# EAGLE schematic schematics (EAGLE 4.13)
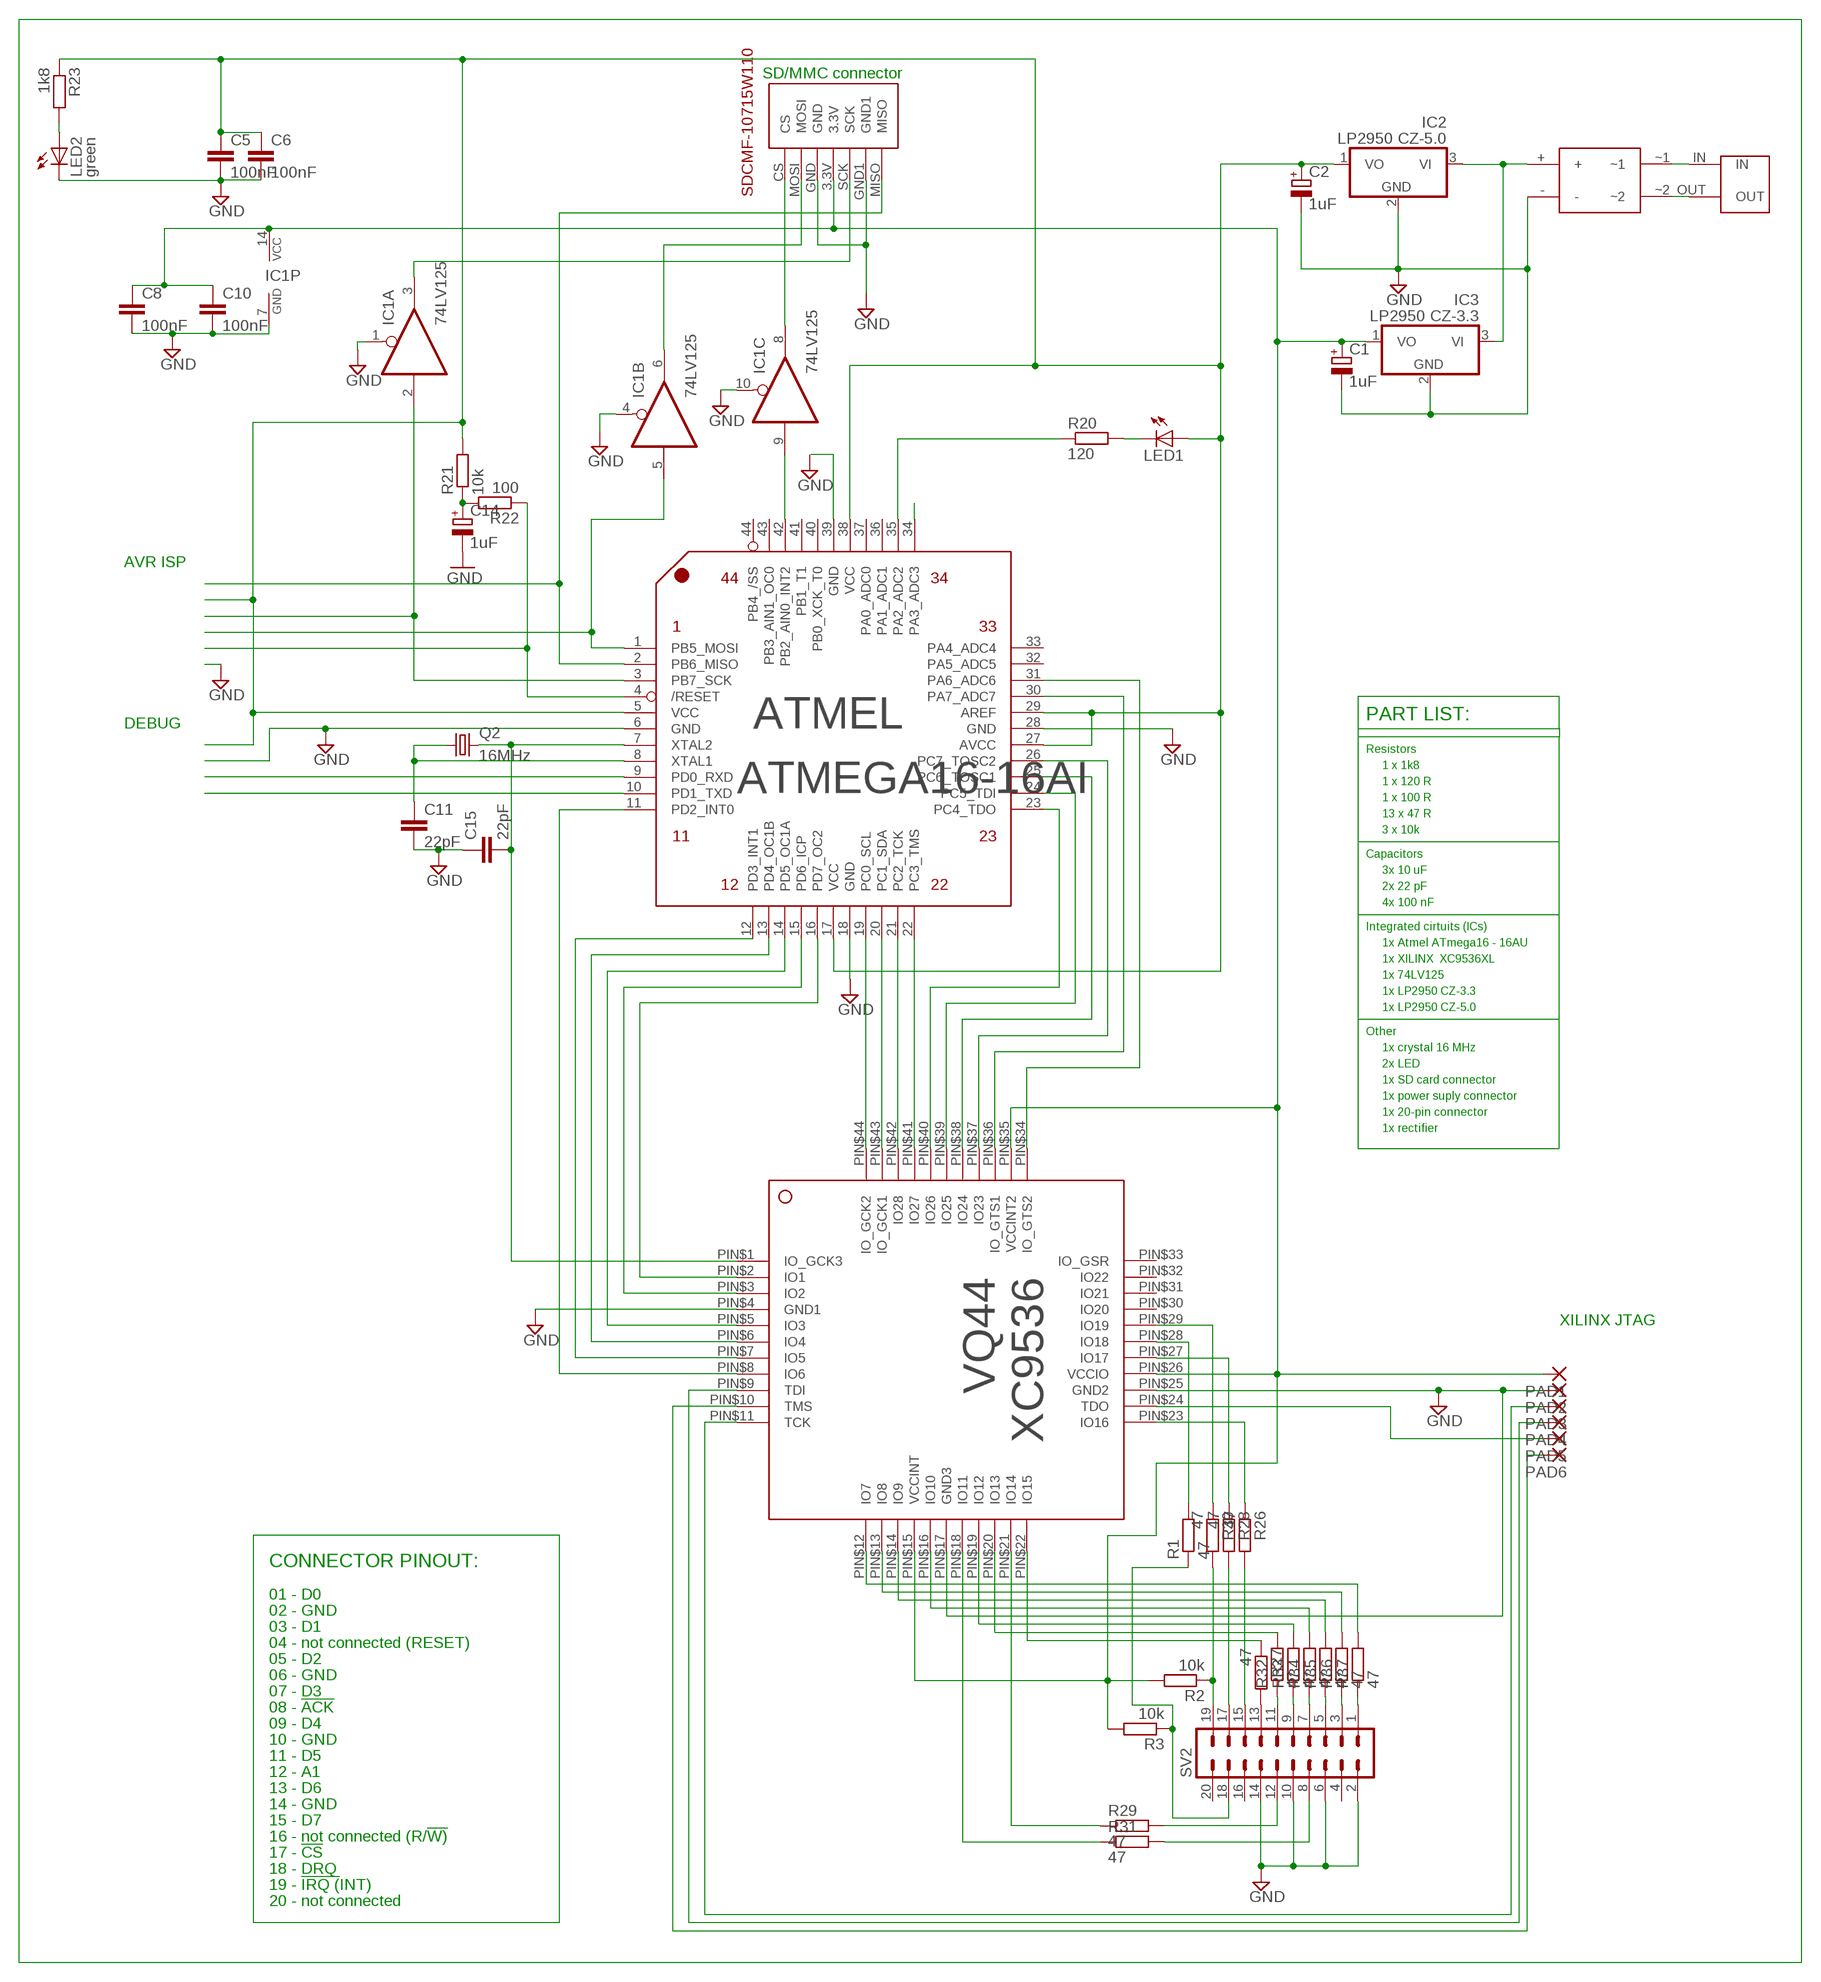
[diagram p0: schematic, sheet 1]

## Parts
ATMEL  ATMEGA16-16AI  [TQFP-44]
C1  1uF  CPOL-EUE2,5-6E  [E2,5-6E]
C2  1uF  CPOL-EUE2,5-6E  [E2,5-6E]
C5  100nF  C-EUC0805K  [C0805K]
C6  100nF  C-EUC0805K  [C0805K]
C8  100nF  C-EUC0805K  [C0805K]
C10  100nF  C-EUC0805K  [C0805K]
C11  22pF  C-EUC0805K  [C0805K]
C14  1uF  CPOL-EUE2-5  [E2-5]
C15  22pF  C-EUC0805K  [C0805K]
CON  DC_CON  [DC_CON]
IC1  74LV125  74HC125D  [SO14]
IC2  LP2950 CZ-5.0  7805L  [TO92]
IC3  LP2950 CZ-3.3  7805L  [TO92]
LED1  LED3MM  [LED3MM]
LED2  green  LED3MM  [LED3MM]
MMC  MMC_CONNECTOR  [MMC]
PAD1  SMD2  [SMD2]
PAD2  SMD2  [SMD2]
PAD3  SMD2  [SMD2]
PAD4  SMD2  [SMD2]
PAD5  SMD2  [SMD2]
PAD6  SMD2  [SMD2]
Q2  16MHz  CRYTALHC49S  [HC49/S]
R1  47  R-EU_M0805  [M0805]
R2  10k  R-EU_M0805  [M0805]
R3  10k  R-EU_M0805  [M0805]
R20  120  R-EU_M0805  [M0805]
R21  10k  R-EU_M0805  [M0805]
R22  100  R-EU_M0805  [M0805]
R23  1k8  R-EU_M0805  [M0805]
R26  47  R-EU_M0805  [M0805]
R27  47  R-EU_M0805  [M0805]
R28  47  R-EU_M0805  [M0805]
R29  47  R-EU_M0805  [M0805]
R30  47  R-EU_M0805  [M0805]
R31  47  R-EU_M0805  [M0805]
R32  47  R-EU_M0805  [M0805]
R33  47  R-EU_M0805  [M0805]
R34  47  R-EU_M0805  [M0805]
R35  47  R-EU_M0805  [M0805]
R36  47  R-EU_M0805  [M0805]
R37  47  R-EU_M0805  [M0805]
RECT  S80  B80_SMDSMALL  [SMD_B40]
SV2  ML20L  [ML20L]
XILINX  XC9536-VQ44  [VQ44]

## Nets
3.3V: C1.+ C8.1 C10.1 IC1.14(P:VCC) IC3.1(VO) MMC.3.3V PAD1.1(P) R2.2 R3.2 XILINX.PIN$15(VCCINT) XILINX.PIN$26(VCCIO) XILINX.PIN$35(VCCINT2)
5V: ATMEL.5(VCC) ATMEL.17(VCC) ATMEL.27(AVCC) ATMEL.29(AREF) ATMEL.38(VCC) C2.+ C5.1 C6.1 IC2.1(VO) LED1.A R21.2 R23.1
ACK: R1.2 XILINX.PIN$28(IO18)
AD0: R37.2 XILINX.PIN$12(IO7)
AD1: R36.2 XILINX.PIN$13(IO8)
AD2: R35.2 XILINX.PIN$14(IO9)
AD3: R34.2 XILINX.PIN$16(IO10)
AD4: R28.1 XILINX.PIN$27(IO17)
AD5: R26.1 XILINX.PIN$23(IO16)
AD6: R29.1 XILINX.PIN$21(IO14)
AD7: R32.2 XILINX.PIN$20(IO13)
CLK: ATMEL.7(XTAL2) C15.2 Q2.2 XILINX.PIN$1(IO_GCK3)
CS: R33.2 XILINX.PIN$19(IO12)
DRQ: R31.1 XILINX.PIN$18(IO11)
GND: ATMEL.6(GND) ATMEL.18(GND) ATMEL.28(GND) ATMEL.39(GND) C1.- C2.- C5.2 C6.2 C8.2 C10.2 C11.2 C14.- C15.1 IC1.1(A:OE) IC1.4(B:OE) IC1.7(P:GND) IC1.10(C:OE) IC2.2(GND) IC3.2(GND) LED2.K(C) MMC.GND MMC.GND1 PAD2.1(P) RECT.- SV2.2 SV2.6 SV2.10 SV2.14 XILINX.PIN$4(GND1) XILINX.PIN$17(GND3) XILINX.PIN$25(GND2)
N$1: ATMEL.35(PA2_ADC2) R20.1
N$2: ATMEL.19(PC0_SCL) XILINX.PIN$44(IO_GCK2)
N$3: ATMEL.20(PC1_SDA) XILINX.PIN$43(IO_GCK1)
N$4: ATMEL.21(PC2_TCK) XILINX.PIN$42(IO28)
N$5: ATMEL.22(PC3_TMS) XILINX.PIN$41(IO27)
N$6: ATMEL.23(PC4_TDO) XILINX.PIN$40(IO26)
N$7: ATMEL.24(PC5_TDI) XILINX.PIN$39(IO25)
N$8: ATMEL.25(PC6_TOSC1) XILINX.PIN$38(IO24)
N$9: ATMEL.26(PC7_TOSC2) XILINX.PIN$37(IO23)
N$10: ATMEL.30(PA7_ADC7) XILINX.PIN$36(IO_GTS1)
N$11: ATMEL.31(PA6_ADC6) XILINX.PIN$34(IO_GTS2)
N$12: ATMEL.16(PD7_OC2) XILINX.PIN$2(IO1)
N$13: ATMEL.15(PD6_ICP) XILINX.PIN$3(IO2)
N$14: ATMEL.14(PD5_OC1A) XILINX.PIN$5(IO3)
N$15: ATMEL.11(PD2_INT0) XILINX.PIN$8(IO6)
N$16: ATMEL.13(PD4_OC1B) XILINX.PIN$6(IO4)
N$17: ATMEL.12(PD3_INT1) XILINX.PIN$7(IO5)
N$18: R27.2 SV2.13
N$19: R26.2 SV2.15
N$20: R28.2 SV2.17
N$21: R2.1 R30.2 SV2.19
N$22: R29.2 SV2.12
N$23: R31.2 SV2.8
N$24: R32.1 SV2.11
N$25: R33.1 SV2.9
N$26: R34.1 SV2.7
N$27: R35.1 SV2.5
N$28: R36.1 SV2.3
N$29: R37.1 SV2.1
N$31: ATMEL.10(PD1_TXD)
N$32: ATMEL.9(PD0_RXD)
N$33: C14.+ R21.1 R22.2
N$34: PAD3.1(P) XILINX.PIN$11(TCK)
N$35: PAD5.1(P) XILINX.PIN$24(TDO)
N$36: PAD4.1(P) XILINX.PIN$9(TDI)
N$37: PAD6.1(P) XILINX.PIN$10(TMS)
N$38: ATMEL.34(PA3_ADC3)
N$40: ATMEL.8(XTAL1) C11.1 Q2.1
N$44: LED2.A R23.2
N$45: ATMEL.2(PB6_MISO) MMC.MISO
N$47: LED1.K(C) R20.2
N$49: ATMEL.4(/RESET) R22.1
N$50: R27.1 XILINX.PIN$22(IO15)
N$51: ATMEL.42(PB2_AIN0_INT2) IC1.9(C:I)
N$52: IC1.8(C:O) MMC.CS
N$53: ATMEL.1(PB5_MOSI) IC1.5(B:I)
N$54: IC1.6(B:O) MMC.MOSI
N$55: ATMEL.3(PB7_SCK) IC1.2(A:I)
N$56: IC1.3(A:O) MMC.SCK
N$57: R1.1 R3.1 SV2.18
N$58: R30.1 XILINX.PIN$29(IO19)
URAW: IC2.3(VI) IC3.3(VI) RECT.+
~1: CON.IN RECT.~1
~2: CON.OUT RECT.~2
Unconnected: ATMEL.32(PA5_ADC5) ATMEL.33(PA4_ADC4) ATMEL.36(PA1_ADC1) ATMEL.37(PA0_ADC0) ATMEL.40(PB0_XCK_T0) ATMEL.41(PB1_T1) ATMEL.43(PB3_AIN1_OC0) ATMEL.44(PB4_/SS) IC1.11(D:O) IC1.12(D:I) IC1.13(D:OE) SV2.4 SV2.16 SV2.20 XILINX.PIN$30(IO20) XILINX.PIN$31(IO21) XILINX.PIN$32(IO22) XILINX.PIN$33(IO_GSR)

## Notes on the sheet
- SD/MMC connector
- AVR ISP
- PART LIST:
- DEBUG
- Resistors
- 1 x 1k8
- 1 x 120 R
- 1 x 100 R
- 13 x 47 R
- 3 x 10k
- Capacitors
- 3x 10 uF
- 2x 22 pF
- 4x 100 nF
- Integrated cirtuits (ICs)
- 1x Atmel ATmega16 - 16AU
- 1x XILINX  XC9536XL
- 1x 74LV125
- 1x LP2950 CZ-3.3
- 1x LP2950 CZ-5.0
- Other
- 1x crystal 16 MHz
- 2x LED
- 1x SD card connector
- 1x power suply connector
- 1x 20-pin connector
- 1x rectifier
- XILINX JTAG
- CONNECTOR PINOUT:
- 01 - D0
- 02 - GND
- 03 - D1
- 04 - not connected (RESET)
- 05 - D2
- 06 - GND
- 07 - D3
- 08 - !ACK
- 09 - D4
- 10 - GND
- 11 - D5
- 12 - A1
- 13 - D6
- 14 - GND
- 15 - D7
- 16 - not connected (R/!W)
- 17 - !CS
- 18 - DRQ
- 19 - !IRQ (!INT)
- 20 - not connected

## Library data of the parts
ATMEL = Atmel_Prototype_Header:ATMEGA16: 8-bit AVR Microcontroller with 16K Bytes In-System Programmable Flash
C1 C2 C14 = rcl:CPOL-EU: POLARIZED CAPACITOR, European symbol
C5 C6 C8 C10 C11 C15 = rcl:C-EU: CAPACITOR, European symbol
CON = jookie:DC_CON
IC1 = 74xx-eu:74*125: Quad bus BUFFER, 3-state
IC2 IC3 = linear:78*: Positive VOLTAGE REGULATOR
LED1 LED2 = led:LED: LED
MMC = jookie:MMC_CONNECTOR
PAD1-PAD6 = wirepad:SMD2: SMD PAD
Q2 = crystal:CRYTAL: CRYSTAL
R1-R3 R20-R23 R26-R37 = rcl:R-EU_: RESISTOR, European symbol
RECT = jookie:B80_SMD
SV2 = con-harting-ml:ML20: HARTING
XILINX = xilinx:XC9536-VQ44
